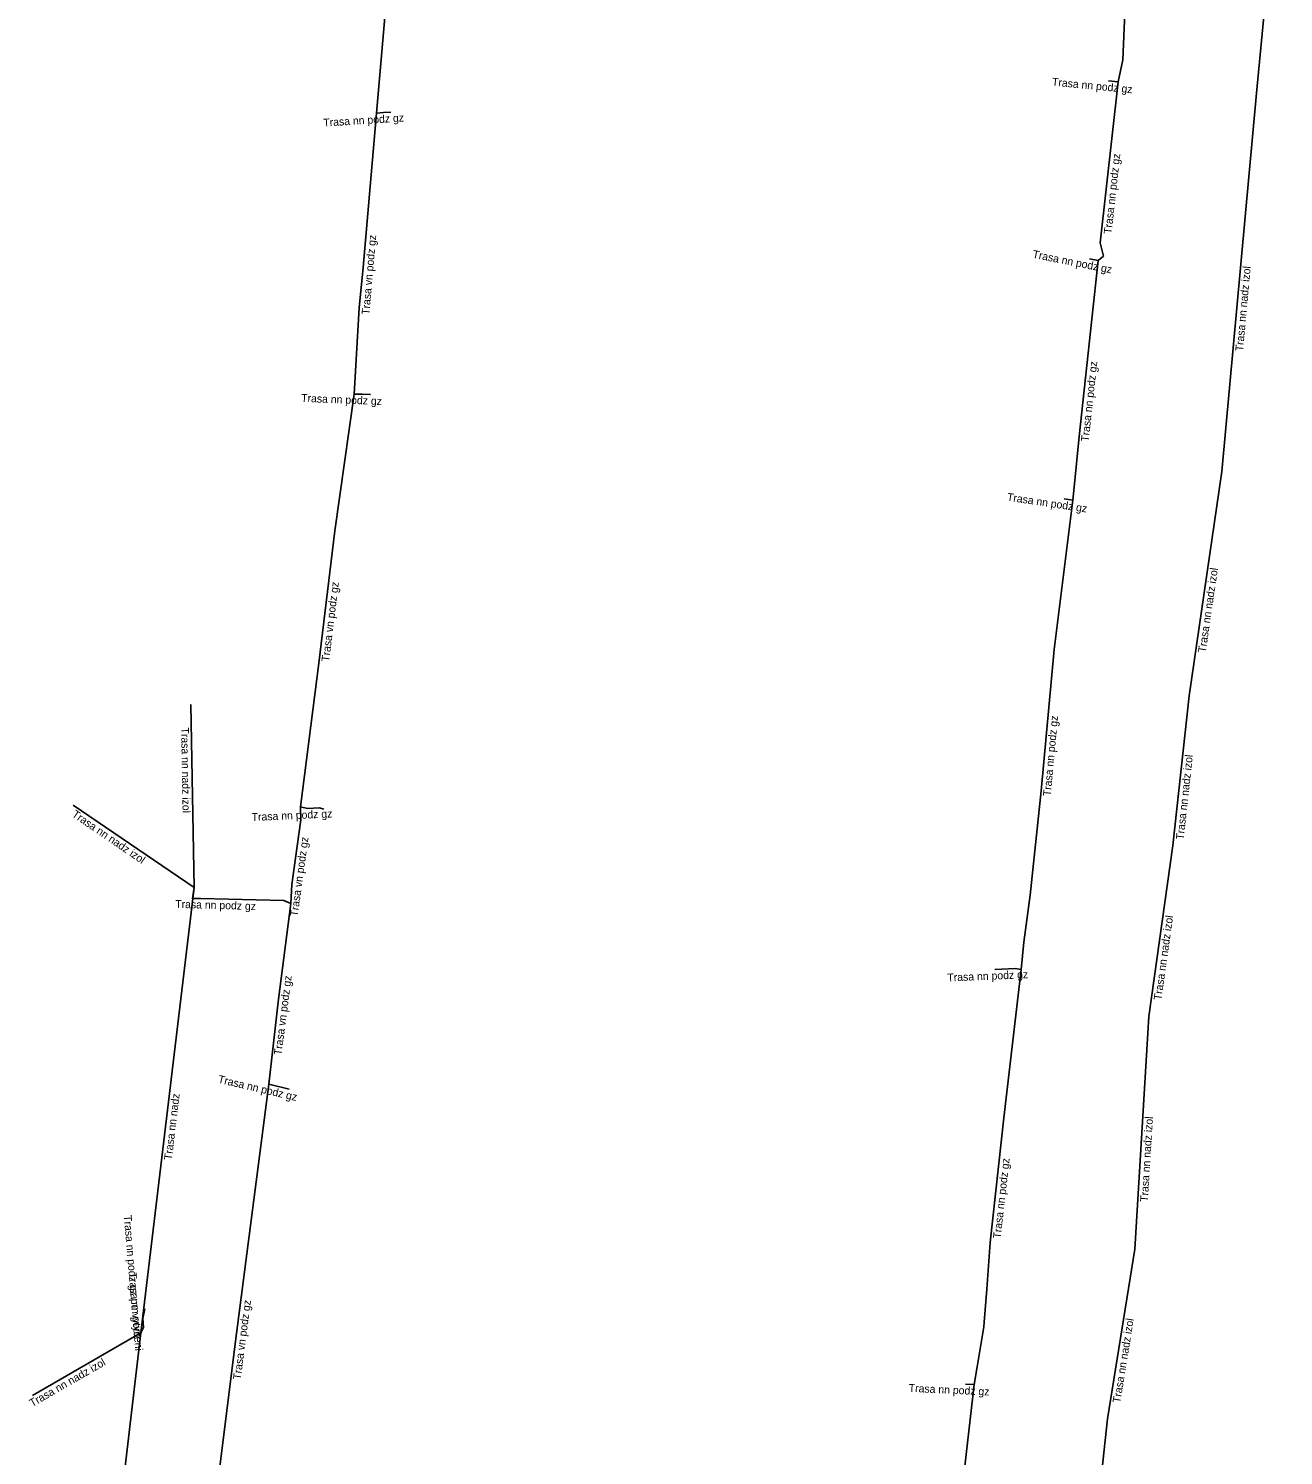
# Model space of a CAD drawing. Extents: x -772942 to -772530, y -1033745 to -1033298.
# Drawn here: x -772758.5 to -772678.3, y -1033493.3 to -1033402.1 of the extents above; entities that cross this region are included whole.
import ezdxf

# ---------------------------------------------------------------- set-up
doc = ezdxf.new("R2010")
doc.units = 0
for name, color, linetype in [('Popiskový text - Ostatní atributy Trasy', 7, 'Continuous'), ('Spojnice NN', 7, 'Continuous'), ('Spojnice VN', 7, 'Continuous')]:
    doc.layers.add(name, color=color, linetype=linetype)

msp = doc.modelspace()

# ---------------------------------------------------------------- linework, layer by layer
at = {"layer": 'Spojnice NN'}
for points in [[(-772678.288, -1033388.133), (-772680.02, -1033406.233)], [(-772688.86, -1033405.5), (-772688.56, -1033404.11), (-772688.44, -1033401.09), (-772688.15, -1033398.38), (-772687.35, -1033390.47)], [(-772690.14, -1033416.93), (-772689.79, -1033416.65), (-772690, -1033415.8), (-772688.86, -1033405.5)], [(-772688.86, -1033405.5), (-772689.472, -1033405.441)], [(-772680.02, -1033406.233), (-772682.226, -1033430.408)], [(-772735.373, -1033407.443), (-772735.838, -1033407.473), (-772736.269, -1033407.5)], [(-772691.76, -1033432.25), (-772691.68, -1033431.41), (-772691.36, -1033428.17), (-772690.14, -1033416.93)], [(-772690.14, -1033416.93), (-772690.692, -1033416.819)], [(-772737.709, -1033425.464), (-772737.199, -1033425.468), (-772736.662, -1033425.49)], [(-772682.226, -1033430.408), (-772684.318, -1033444.749)], [(-772695.07, -1033462.26), (-772694.89, -1033460.51), (-772694.48, -1033457.5), (-772693.79, -1033450.83), (-772692.96, -1033441.79), (-772691.76, -1033432.25)], [(-772691.76, -1033432.25), (-772692.32, -1033432.166)], [(-772748.148, -1033445.305), (-772747.943, -1033457.016)], [(-772684.318, -1033444.749), (-772685.368, -1033454.333)], [(-772755.665, -1033451.736), (-772747.943, -1033457.016)], [(-772741.144, -1033451.847), (-772740.689, -1033451.95), (-772739.93, -1033451.916), (-772739.64, -1033451.991)], [(-772685.368, -1033454.333), (-772686.894, -1033465.265)], [(-772751.34, -1033485.48), (-772747.943, -1033457.016)], [(-772741.761, -1033458.038), (-772742.202, -1033457.849), (-772747.522, -1033457.702), (-772748.054, -1033457.719), (-772747.943, -1033457.016)], [(-772698.06, -1033488.79), (-772697.87, -1033487.64), (-772697.45, -1033485.09), (-772697.42, -1033484.8), (-772697.25, -1033482.69), (-772697.05, -1033479.7), (-772696.16, -1033471.74), (-772695.07, -1033462.26)], [(-772695.07, -1033462.26), (-772695.45, -1033462.19), (-772696.744, -1033462.243)], [(-772687.79, -1033480.12), (-772686.894, -1033465.265)], [(-772743.155, -1033469.585), (-772741.857, -1033469.89)], [(-772689.543, -1033490.976), (-772687.79, -1033480.12)], [(-772751.34, -1033485.48), (-772751.18, -1033485.14), (-772751.23, -1033484.55), (-772751.1, -1033483.95)], [(-772751.34, -1033485.48), (-772751.18, -1033485.14), (-772751.23, -1033484.55), (-772751.1, -1033483.95)], [(-772758.284, -1033489.475), (-772751.34, -1033485.48)], [(-772754.975, -1033516.403), (-772751.34, -1033485.48)], [(-772699.63, -1033503.41), (-772698.66, -1033493.99), (-772698.06, -1033488.79)], [(-772698.06, -1033488.79), (-772698.617, -1033488.764)], [(-772690.717, -1033501.871), (-772689.543, -1033490.976)]]:
    msp.add_lwpolyline(points, dxfattribs=at)
at = {"layer": 'Spojnice VN'}
for points in [[(-772733.276, -1033375.367), (-772733.873, -1033380.137), (-772734.198, -1033384.941), (-772734.747, -1033389.83), (-772736.269, -1033407.5)], [(-772736.269, -1033407.5), (-772737.127, -1033417.37), (-772737.393, -1033419.955), (-772737.709, -1033425.464)], [(-772737.709, -1033425.464), (-772738.938, -1033434.211), (-772739.971, -1033442.662), (-772741.144, -1033451.847)], [(-772741.144, -1033451.847), (-772741.127, -1033452.69), (-772741.692, -1033456.808), (-772741.761, -1033458.038)], [(-772741.761, -1033458.038), (-772742.546, -1033464.154), (-772743.155, -1033469.585)], [(-772743.155, -1033469.585), (-772745.232, -1033485.512), (-772746.375, -1033494.71), (-772746.919, -1033499.528)]]:
    msp.add_lwpolyline(points, dxfattribs=at)

# ---------------------------------------------------------------- texts
at = {"layer": 'Popiskový text - Ostatní atributy Trasy'}
for s, rotation, p in [('Trasa nn podz gz', 354.4934, (-772693.104, -1033405.744)), ('Trasa nn podz gz', 3.69139, (-772739.665, -1033408.371)), ('Trasa nn podz gz', 83.68423, (-772689.285, -1033415.25)), ('Trasa vn podz gz', 85.03176, (-772736.739, -1033420.414)), ('Trasa nn podz gz', 348.6302, (-772694.362, -1033416.744)), ('Trasa nn nadz izol', 84.78613, (-772680.875, -1033422.751)), ('Trasa nn podz gz', 83.80531, (-772690.746, -1033428.529)), ('Trasa nn podz gz', 357.654, (-772741.103, -1033425.958)), ('Trasa nn podz gz', 351.46923, (-772695.987, -1033432.274)), ('Trasa nn nadz izol', 81.70049, (-772683.262, -1033442.016)), ('Trasa vn podz gz', 83.03108, (-772739.307, -1033442.592)), ('Trasa nn podz gz', 84.75414, (-772693.17, -1033451.186)), ('Trasa nn nadz izol', 271.00286, (-772748.772, -1033446.783)), ('Trasa nn nadz izol', 83.74775, (-772684.675, -1033453.976)), ('Trasa nn nadz izol', 325.63721, (-772755.795, -1033452.435)), ('Trasa nn podz gz', 2.56489, (-772744.254, -1033452.76)), ('Trasa vn podz gz', 82.18765, (-772741.322, -1033458.888)), ('Trasa nn podz gz', 358.41723, (-772749.154, -1033458.307)), ('Trasa nn nadz izol', 82.05342, (-772686.094, -1033464.236)), ('Trasa vn podz gz', 82.68597, (-772742.353, -1033467.751)), ('Trasa nn podz gz', 2.34542, (-772699.768, -1033463.017)), ('Trasa nn podz gz', 346.7767, (-772746.445, -1033469.48)), ('Trasa nn nadz', 83.1943, (-772749.369, -1033474.45)), ('Trasa nn nadz izol', 86.54831, (-772686.958, -1033477.114)), ('Trasa nn podz gz', 83.62031, (-772696.37, -1033479.469)), ('Trasa nn podz gz po vytyceni', 274.844, (-772752.44, -1033477.973)), ('Trasa nn podz', 274.844, (-772752.129, -1033481.645)), ('Trasa vn podz gz', 82.57013, (-772744.966, -1033488.493)), ('Trasa nn nadz izol', 80.8272, (-772688.725, -1033489.985)), ('Trasa nn nadz izol', 29.91498, (-772758.292, -1033490.23)), ('Trasa nn podz gz', 357.32745, (-772702.258, -1033489.245))]:
    msp.add_text(s, height=0.5, rotation=rotation, dxfattribs=at).set_placement(p)

doc.saveas('drawing.dxf')
